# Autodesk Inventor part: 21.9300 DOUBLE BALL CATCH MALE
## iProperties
Created: 2010-11
Part Number: 21.9300 DOUBLE BALL CATCH MALE
Document SubType Name: Modeling
Designer: Administrator
Density: 1.06 g/cm^3
Material: ABS Plastic
Mass: 18.689 g
Surface Area: 68.48 cm^2
Volume: 17.6311 cm^3
Author: Administrator
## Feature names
1. Base1
